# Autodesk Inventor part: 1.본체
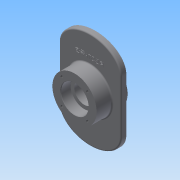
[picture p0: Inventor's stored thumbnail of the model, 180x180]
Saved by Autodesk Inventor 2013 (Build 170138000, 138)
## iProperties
Created: 2015-02
Part Number: 1.본체
Material: 일반
Document SubType Name: Modeling
Designer: Administrator
Density: 1 g/cm^3
Author: Administrator
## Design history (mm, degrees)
sketch "스케치1"
  geometry: L1 (-70, 60)-(-70, -60); L2 (70, 60)-(70, -60); L3 (-70, 0)-(70, 0); L4 (0, 110)-(0, 0); L5 (-70, 60)-(70, 60); 3 further points; 2 other entities
  constraints: 10 end point, 4 midpoint, 3 horizontal, 3 parallel, 1 coincident, 1 perpendicular, 1 symmetric about line, 1 vertical, 9 other
  dimensions: "d4" = 140 distance between parallel lines of L2 L1; "d5" = 60 distance of L2.start L3.end; "d58" = 50 vertical distance of L2.start L4.start
extrude "돌출1" new body sketch "스케치1" distance "d6" = 12; taper "d7" = 0 deg
sketch "스케치2"
  geometry: C1 r 50 at (0, 0); 1 further point
  constraints: 1 centre point, 1 coincident
  dimensions: "d8" = 100 diameter of C1
extrude "돌출2" join sketch "스케치2" distance "d10" = 35; taper "d11" = 0 deg
sketch "스케치3"
  geometry: C1 r 50 at (0, 0); 1 further point
  constraints: 1 centre point, 1 coincident
  dimensions: "d12" = 100 diameter of C1
extrude "돌출3" join sketch "스케치3" distance "d14" = 23; taper "d15" = 0 deg
sketch "스케치4"
  geometry: C1 r 50 at (0, 0) reference; C2 r 31 at (0, 0)
  constraints: 1 centre point, 1 coincident
  dimensions: "d16" = 62 diameter of C2
extrude "돌출4" cut sketch "스케치4" distance "d18" = 22; taper "d19" = 0 deg
sketch "스케치5"
  geometry: C1 r 50 at (0, 0) reference; C2 r 31 at (0, 0)
  constraints: 1 centre point, 1 coincident
  dimensions: "d20" = 62 diameter of C2
extrude "돌출5" cut sketch "스케치5" distance "d22" = 22; taper "d23" = 0 deg
sketch "스케치6"
  geometry: C1 r 31 at (0, 0) reference; C2 r 22.5 at (0, 0)
  constraints: 1 centre point, 1 coincident
  dimensions: "d24" = 45 diameter of C2
extrude "돌출6" cut sketch "스케치6" stored distance "d26" = 22; taper "d27" = 0 deg
sketch "스케치8"
  geometry: L1 (0, 50)-(0, 0); L2 (0, 0)-(-28.991, 28.991); C1 r 31 at (0, 0) reference; 4 further points
  constraints: 4 end point, 1 coincident, 1 vertical, 1 vertical alignment, 6 other
  dimensions: "d30" = 45 deg angle of L2 L1; "d31" = 41 distance of L1.end L2.end; "d34" = 360 deg dimension on C1.centre point (-28.991, 28.991) (derived)
hole "구멍1" sketch "스케치8" at (-28.991, 28.991), (-28.991, -28.991), (28.991, -28.991), (28.991, 28.991) diameter "d36" = 5.459; stored, may be unused: countersink angle "d40" = 90 deg, drill point angle "d42" = 118 deg; dims "d37" = 10, "d38" = 4, "d39" = 2, "d41" = 13
sketch "스케치9"
  geometry: L1 (0, 50)-(0, 0); L2 (0, 0)-(-28.991, 28.991); C1 r 31 at (0, 0) reference; 4 further points
  constraints: 4 end point, 1 coincident, 1 vertical, 1 vertical alignment, 6 other
  dimensions: "d43" = 45 deg angle of L2 L1; "d44" = 41 distance of L1.end L2.end; "d47" = 360 deg dimension on C1.centre point (-28.991, 28.991) (derived)
hole "구멍2" sketch "스케치9" at (-28.991, 28.991), (-28.991, -28.991), (28.991, -28.991), (28.991, 28.991) diameter "d49" = 5.459; stored, may be unused: countersink angle "d53" = 90 deg, drill point angle "d55" = 118 deg; dims "d50" = 10, "d51" = 4, "d52" = 2, "d54" = 13
sketch "스케치10"
  geometry: L1 (70, -60)-(70, 60) reference; L2 (-70, 60)-(-70, -60) reference; L3 (53, 60)-(53, -60); L4 (-53, -60)-(-53, 60); L5 (70, -60)-(70, 60) reference; L6 (-70, 60)-(-70, -60) reference; C1 r 50 at (0, 0) reference; C2 r 50 at (0, 0) reference; 6 further points; 4 other entities
  constraints: 4 end point, 3 parallel, 2 horizontal alignment, 8 other
  dimensions: "d61" = 17 distance between parallel lines of L1 L3
  node "투영된 루프1"
fillet "모깎기1" dims "d56" = 0.3
fillet "모깎기2" dims "d57" = 3
sketch "스케치11"
  geometry: C1 r 53 at (0, 0) reference; 1 further point
  constraints: 1 vertical alignment, 1 other
  dimensions: "d62" = 65 distance of C1.centre point (0, 65)
feature "엠보싱1" sketch "스케치11" dims "d4" = 140, "d5" = 60, "d58" = 50, "d63" = 1, "d64" = 0
chamfer "모따기1" distance "d65" = 1; stored, may be unused: second distance "d66" = 2, angle "d67" = 45 deg
chamfer "모따기2" distance "d68" = 1; stored, may be unused: second distance "d69" = 2, angle "d70" = 45 deg
node "솔리드1"
